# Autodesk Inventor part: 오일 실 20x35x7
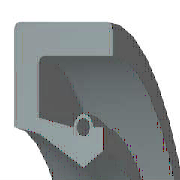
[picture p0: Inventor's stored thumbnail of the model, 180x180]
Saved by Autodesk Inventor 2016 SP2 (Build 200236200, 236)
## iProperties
IsCustomPart: 1
Created: 2012-02
Part Number: 오일 실 20x35x7
Material: 고무
Description: 회전 샤프트 립 유형 실 2 - 금속 케이스
Document SubType Name: Modeling
Standard: ISO 6194/1
Designer: mduedu
Standards Organization: ISO
Language: ko-KR
Size Designation: 20x35x7-유형 2
Categories: <MemberInstance><Categories><Category DisplayName="샤프트 부품" InternalName="7f7aeb1f-a693-4053-b835-cee3144e0d98" Mnemonic="SHFT"><Category DisplayName="실링" Intern
Density: 0.93 g/cm^3
Appearance: 고무 - 검은색 - 버전 1.1
Author: mduedu
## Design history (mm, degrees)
node "WorkPlane2"
node "WorkPoint1"
node "WorkPlane3"
body "Solid1"
node "스케치1"
revolve "회전1" stored, may be unused: angle "d37" = 360 deg
fillet "모깎기1" dims "d38" = 0.35 (= 0.05 x b)
sketch "스케치2"
  geometry: L1 (16, -0.35)-(16.8, -0.35); L2 (16, 0)-(16, -0.35); L3 (17.5, 0)-(16, 0); L4 (17.5, -7)-(17.5, 0); L5 (12.22, -7)-(17.5, -7); L6 (11.283, -4.2)-(12.22, -7); L7 (10.601, -3.72)-(11.283, -4.2); L8 (10, -1.925)-(10.601, -3.72); L9 (10.789, -1.05)-(10, -1.925); L10 (12.664, -1.05)-(10.789, -1.05); L11 (12.664, -1.925)-(12.664, -1.05); L12 (12.664, -5.6)-(12.664, -3.325); L13 (13.664, -5.6)-(12.664, -5.6); L14 (13.664, -6.3)-(13.664, -5.6); L15 (16.8, -6.3)-(13.664, -6.3); L16 (16.8, -0.35)-(16.8, -6.3); L17 (0, -15.959)-(0, 2.029); L18 (0, -15.959)-(0, 2.029); L19 (0, -19.557)-(0, 5.626) reference; L20 (-5.2, 0)-(31.2, 0) reference; A1 r 0.7 centre (12.664, -2.625) between (12.664, -3.325) and (12.664, -1.925)
  constraints: 36 end point, 7 vertical, 6 horizontal, 2 collinear, 2 point on circle, 1 centre point, 1 parallel, 1 point on line
  dimensions: "d2" = 0.35 distance of L2.start L1.start (= 0.05 x b); "d4" = 7 distance of L4.start L3.start (= b); "d6" = 0.7 horizontal distance of L1.end L3.start (= 0.1 x b); "d8" = 0.7 horizontal distance of L15.start L4.start (= 0.1 x b); "d10" = 0.7 distance of L14.start L13.start (= 0.1 x b); "d12" = 0.7 vertical distance of L1.end L10.start (= 0.1 x b); "d14" = 0.875 distance of L11.start L10.start (= 0.125 x b); "d16" = 0.7 radius of A1 (= 0.1 x b); "d18" = 0 horizontal distance of A1.centre L12.end; "d20" = 0.875 vertical distance of L9.start L8.start (= 0.125 x b); "d22" = 1.79487 vertical distance of L8.start L7.start (= 0.25641 x b); "d24" = 2.8 vertical distance of L6.start L5.start (= 0.4 x b); "d26" = 1.5 distance of L3.start L2.start (= 0.1 x dd - 0.1 x Diam); "d28" = 0.78947 horizontal distance of L9.start L8.start (= 0.0526316 x dd - 0.0526316 x Diam); "d30" = 1.875 distance of L10.start L9.start (= 0.125 x dd - 0.125 x Diam); "d32" = 1 distance of L13.start L12.start (= 0.0666667 x dd - 0.0666667 x Diam); "d34" = 0.9375 horizontal distance of L6.start L5.start (= 0.0625 x dd - 0.0625 x Diam); "d36" = 0.68182 horizontal distance of L7.start L6.start (= 0.0454545 x dd - 0.0454545 x Diam); "msp_d39" = 20 diameter of L8.start L17 (= Diam); "msp_d40" = 35 diameter of L4 L17 (= dd)
other parameters: "dd" = 35 [user parameter; used in 7 equation terms], "Diam" = 20 [user parameter; used in 7 equation terms], "b" = 7 [user parameter; used in 13 equation terms], "d0" = -7 (computed from b), "d1" = 0.4 (derived), "d3" = 8 (derived), "d5" = 0.8 (derived), "d7" = 0.8 (derived), "d9" = 0.8 (derived), "d11" = 0.8 (derived), "d13" = 1 (derived), "d15" = 0.8 (derived), "d17" = 0 (derived), "d19" = 1 (derived), "d21" = 2.05128 (derived), "d23" = 3.2 (derived), "d25" = 2 (derived), "d27" = 1.05263 (derived), "d29" = 2.5 (derived), "d31" = 1.33333 (derived), "d33" = 1.25 (derived), "d35" = 0.90909 (derived), "d42" = 0
